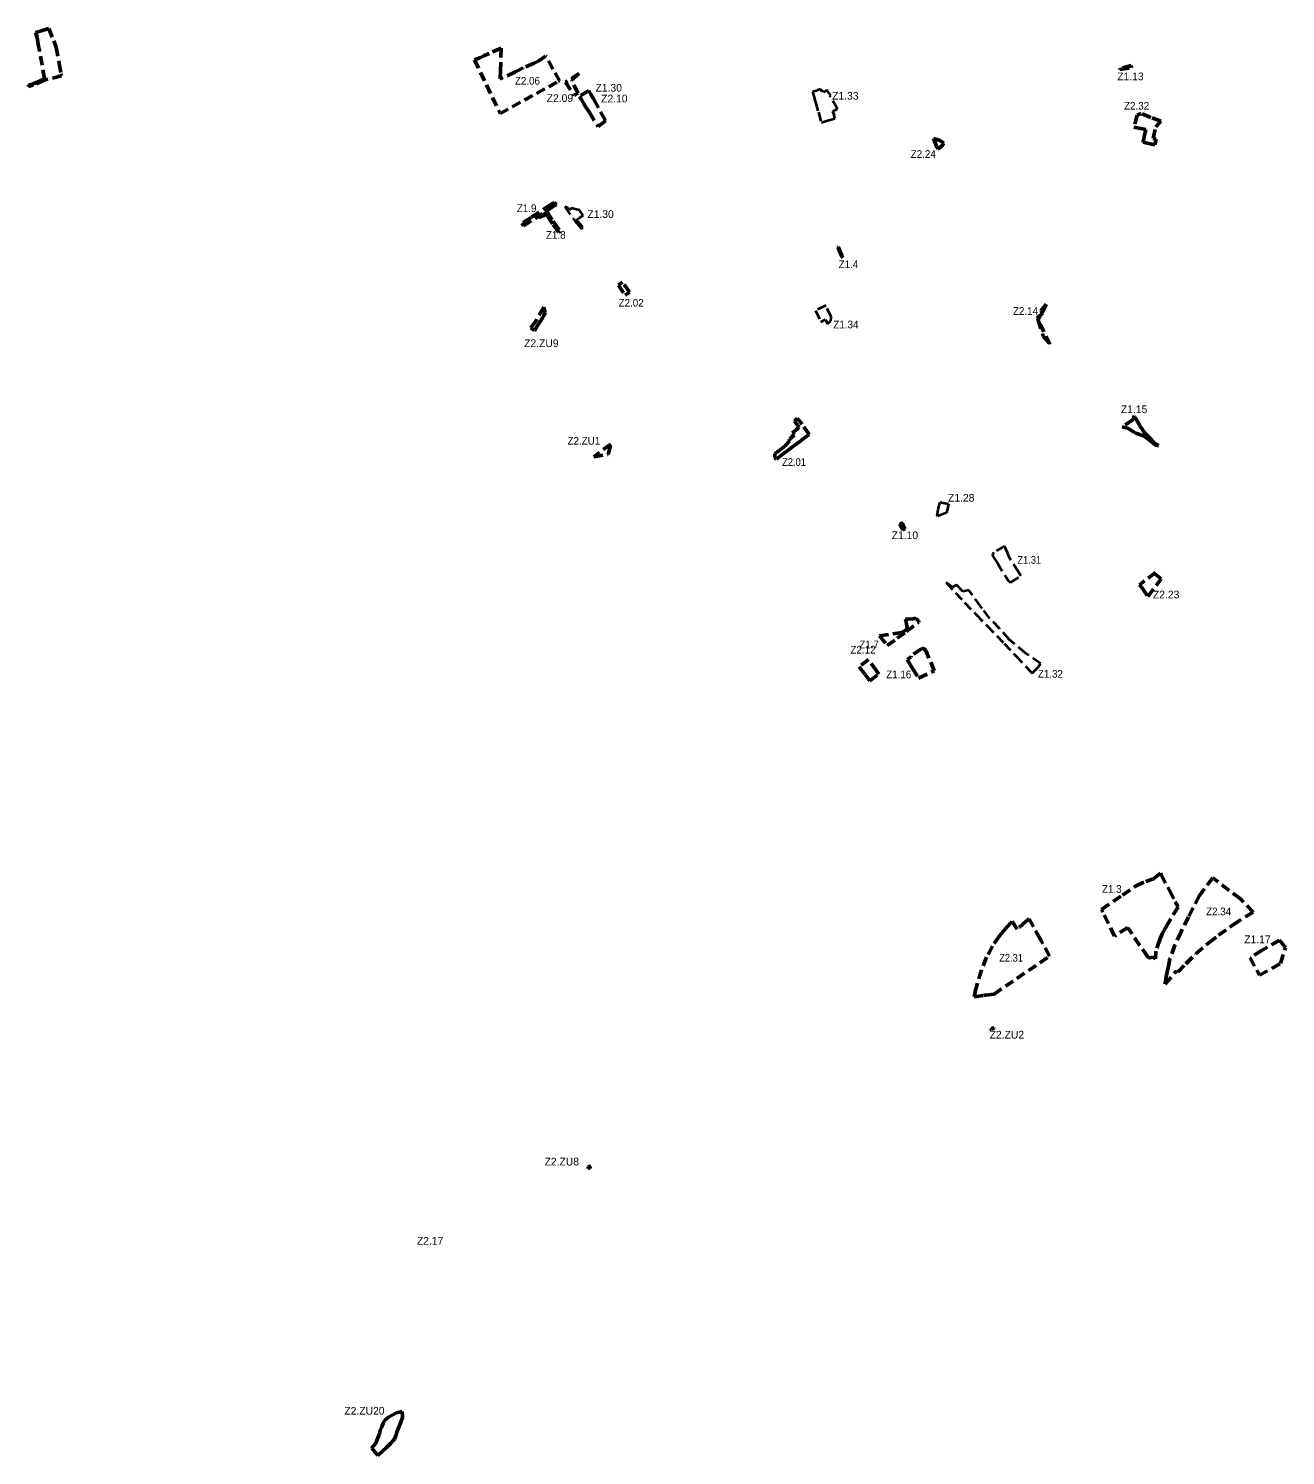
# Model space of a CAD drawing. Extents: x -650368 to -643203, y -1074215 to -1066658.
# Drawn here: x -649708 to -646290, y -1074215 to -1070336 of the extents above; entities that cross this region are included whole.
import ezdxf
from ezdxf.enums import TextEntityAlignment as Align

# ---------------------------------------------------------------- set-up
doc = ezdxf.new("R2010")
doc.units = 0
doc.header["$LTSCALE"] = 8.4
doc.linetypes.add('MEDIUM_DASHED', pattern=[4.5, 3, -1.5])
for name, color, linetype, lineweight in [('57', 7, 'MEDIUM_DASHED', 40), ('58', 7, 'MEDIUM_DASHED', 53), ('59', 7, 'MEDIUM_DASHED', 53)]:
    doc.layers.add(name, color=color, linetype=linetype, lineweight=lineweight)
for name, color, linetype in [('60', 7, 'Continuous'), ('61', 7, 'Continuous'), ('62', 7, 'Continuous')]:
    doc.layers.add(name, color=color, linetype=linetype)

msp = doc.modelspace()

# ---------------------------------------------------------------- linework, layer by layer
at = {"layer": '57', "lineweight": 53}
for points in [[(-649689.02, -1070346.94), (-649670.28, -1070341.35), (-649653.03, -1070336.2), (-649639.561, -1070370), (-649633, -1070386.46), (-649624.97, -1070431.24), (-649620.17, -1070459.09), (-649619.72, -1070461.73), (-649618.85, -1070465.12), (-649663.84, -1070475.94), (-649695.44, -1070490.03), (-649708.08, -1070493.61), (-649708.37, -1070489.38), (-649702.69, -1070488.94), (-649686.94, -1070482.59), (-649664.82, -1070473.32), (-649678.92, -1070395.81), (-649680.99, -1070384.52), (-649683.08, -1070373.11), (-649685.31, -1070360.88)], [(-646739.83, -1070444.94), (-646739.74, -1070447.98), (-646708.18, -1070442.69), (-646708.99, -1070436.76)], [(-648366.98, -1070865.44), (-648362.519, -1070872.788), (-648303.624, -1070834.844), (-648283.19, -1070821.23), (-648272.45, -1070814.075), (-648278.832, -1070808.761), (-648282.44, -1070810.84), (-648287.74, -1070814.32), (-648341.58, -1070849.98)], [(-648320.02, -1070850.16), (-648297.39, -1070835.36), (-648281.37, -1070860.23), (-648279.39, -1070862.98), (-648262.4, -1070886.58), (-648267.24, -1070889.9), (-648283.46, -1070865.74), (-648284.02, -1070864.91), (-648298.78, -1070842.92), (-648305.33, -1070843.62)], [(-647507.79, -1070930.48), (-647506.58, -1070929.86), (-647493.71, -1070959.89), (-647495.91, -1070955.93), (-647496.37, -1070956.17)], [(-647330.34, -1071678.82), (-647339.211, -1071683.431), (-647330.73, -1071700.09), (-647324.21, -1071696.2), (-647331.65, -1071681.7)], [(-647393.87, -1071987.45), (-647372.56, -1072013.58), (-647345.75, -1071993.72), (-647320.41, -1071975.27), (-647287.04, -1071950.34), (-647287.83, -1071945.52), (-647294.62, -1071939.95), (-647299.8, -1071940.18), (-647303.12, -1071940.66), (-647311.9, -1071942.01), (-647322.73, -1071940.89), (-647322.26, -1071943.87), (-647321.38, -1071949.5), (-647320.37, -1071955.14), (-647319.44, -1071960.39), (-647318.12, -1071967.77), (-647332.2, -1071978.11)], [(-646789.83, -1072730.68), (-646732.95, -1072691.68), (-646697.89, -1072667.65), (-646669.6, -1072654.53), (-646648.27, -1072647.48), (-646629.86, -1072632.07), (-646627.32, -1072636.95), (-646605.23, -1072679.37), (-646589.37, -1072709.83), (-646581.92, -1072723.91), (-646612.11, -1072774.56), (-646612.76, -1072775.67), (-646612.4, -1072775.05), (-646616.6, -1072782.31), (-646616.97, -1072782.9), (-646624.81, -1072797.42), (-646631.08, -1072812.68), (-646642.404, -1072844.195), (-646643.445, -1072864.732), (-646651.14, -1072860.57), (-646662.12, -1072863.28), (-646664.42, -1072859.9), (-646716.21, -1072783.78), (-646718.72, -1072780.09), (-646754.96, -1072803.29), (-646786.56, -1072737.88)], [(-646360.22, -1072909.57), (-646303.02, -1072877.74), (-646289.63, -1072834.04), (-646305.56, -1072814.43), (-646353.25, -1072841.63), (-646385.86, -1072862.59)]]:
    msp.add_lwpolyline(points, close=True, dxfattribs=at)
at = {"layer": '57'}
for points in [[(-647537.02, -1070503.71), (-647546, -1070508.8), (-647547.21, -1070505.8), (-647551.72, -1070507.63), (-647554.53, -1070500.69), (-647562.6, -1070503.96), (-647562.41, -1070504.46), (-647575.92, -1070508.61), (-647572.58, -1070520.08), (-647569.96, -1070529.21), (-647570.25, -1070529.29), (-647569.06, -1070533.49), (-647568.31, -1070536.13), (-647560.15, -1070563.59), (-647551.93, -1070591.24), (-647538.02, -1070587.26), (-647515.53, -1070580.81), (-647517.04, -1070572.92), (-647515.92, -1070572.48), (-647521.04, -1070561.51), (-647511.26, -1070556.25), (-647507.74, -1070554.36), (-647527.28, -1070521.45), (-647528.84, -1070518.82), (-647526.64, -1070517.92), (-647535.34, -1070505.95)], [(-648207.151, -1070878.029), (-648205.18, -1070880.5), (-648200.86, -1070877.05), (-648202.798, -1070874.754), (-648212.94, -1070862.74), (-648217.85, -1070856.93), (-648218.11, -1070856.44), (-648209.37, -1070850.44), (-648200.17, -1070844.094), (-648209.66, -1070829.88), (-648221.58, -1070827.03), (-648231.22, -1070824.92), (-648237.46, -1070829.68), (-648241.96, -1070823.46), (-648249.5, -1070821.08), (-648222.158, -1070859.221), (-648217.1, -1070865.56)], [(-647229.63, -1071623.27), (-647206.3, -1071628.17), (-647209.092, -1071641.463), (-647211.91, -1071652.25), (-647217.42, -1071654.54), (-647234.94, -1071661.83), (-647237.25, -1071659.7), (-647233.89, -1071643.39), (-647230.86, -1071629.13)], [(-647184.81, -1071848.61), (-647185.62, -1071849.12), (-647194.96, -1071854.93), (-647205.62, -1071847.24), (-647212.66, -1071842.15), (-647163.08, -1071896.13), (-647131.146, -1071929.146), (-647101.07, -1071960.24), (-647055.16, -1072007.74), (-647023.04, -1072041.63), (-646981.35, -1072085.77), (-646978.602, -1072088.66), (-646962.041, -1072072.379), (-646956.04, -1072061.95), (-646996.8, -1072034.35), (-647040.89, -1071996.58), (-647067.53, -1071967.54), (-647095.51, -1071938.39), (-647114.479, -1071912.479), (-647118.79, -1071906.59), (-647151.07, -1071863.08), (-647167.15, -1071866.22)]]:
    msp.add_lwpolyline(points, close=True, dxfattribs=at)
for points in [[(-647539.818, -1071089.2), (-647568.01, -1071102.98), (-647553.01, -1071133.68)], [(-647525.1, -1071121.25), (-647524.95, -1071119.68), (-647539.817, -1071089.199)], [(-647553.01, -1071133.68), (-647540.48, -1071127.55), (-647534.851, -1071139.015), (-647526.04, -1071130.94), (-647525.1, -1071121.25)], [(-647053.43, -1071743.63), (-647083.97, -1071760.74), (-647084.95, -1071761.98), (-647085.71, -1071763.75), (-647086.19, -1071766.95), (-647085.25, -1071770.69), (-647074.99, -1071786.99)], [(-647009.514, -1071823.81), (-647016.12, -1071813.35), (-647039.14, -1071776.9), (-647044.83, -1071763.37), (-647053.43, -1071743.63)], [(-647074.99, -1071786.99), (-647073.19, -1071789.9), (-647044.12, -1071836.68)], [(-647044.12, -1071836.68), (-647040.2, -1071839.6), (-647037.23, -1071841.82), (-647009.514, -1071823.81)]]:
    msp.add_lwpolyline(points, dxfattribs=at)
at = {"layer": '57', "lineweight": 53}
for points in [[(-646669.77, -1071438.64), (-646671.02, -1071436.82), (-646686.04, -1071415.05), (-646701.52, -1071388.41), (-646703.84, -1071399.38), (-646704.58, -1071400.2), (-646734, -1071419.27), (-646719.23, -1071422.46), (-646715.7, -1071424.14), (-646703.15, -1071432.76), (-646696.59, -1071435.91), (-646678.5, -1071442.87)], [(-646678.5, -1071442.87), (-646673.89, -1071444.28), (-646670.05, -1071447.06), (-646662.55, -1071453.44), (-646655.29, -1071458.37), (-646643.4, -1071468.99), (-646638.52, -1071470.05), (-646634.56, -1071469.49), (-646645.57, -1071462.96), (-646654.25, -1071454.23), (-646669.77, -1071438.64)], [(-647271.92, -1072022.5), (-647274.99, -1072021.69), (-647277.91, -1072021.81), (-647280.99, -1072022.86), (-647308.09, -1072041.53), (-647308.4, -1072044.8), (-647318.52, -1072051.32)], [(-647287.34, -1072101.88), (-647244.88, -1072082.33), (-647267.71, -1072027.09)], [(-647267.71, -1072027.09), (-647269.43, -1072024.67), (-647271.92, -1072022.5)], [(-647318.52, -1072051.32), (-647315.92, -1072055.47), (-647303.63, -1072075.43), (-647287.34, -1072101.88)]]:
    msp.add_lwpolyline(points, dxfattribs=at)
at = {"layer": '58'}
for points in [[(-648495.666, -1070421.476), (-648425.835, -1070567.021), (-648267.801, -1070480.55), (-648263.859, -1070478.393), (-648282.01, -1070446.35), (-648302.01, -1070411.05), (-648320.24, -1070423.64), (-648332.97, -1070430.18), (-648362.79, -1070443.63), (-648363.1, -1070443.1), (-648383.61, -1070453.86), (-648426.05, -1070473.34), (-648425.71, -1070468.87), (-648424.47, -1070452.7), (-648423.56, -1070413.35), (-648423.005, -1070389.357), (-648455.85, -1070404.19), (-648457.94, -1070405.13), (-648469.77, -1070410.47), (-648481.18, -1070415.62)], [(-648184.54, -1070505.07), (-648210.19, -1070521.07), (-648203.83, -1070531.25), (-648197.59, -1070541.27), (-648190.71, -1070552.3), (-648182.98, -1070564.68), (-648159.23, -1070602.75), (-648138.93, -1070587.1), (-648140.05, -1070585.09), (-648166.63, -1070537.28), (-648172.96, -1070525.9), (-648178.7, -1070515.58), (-648184.54, -1070505.07)], [(-646701.87, -1070603.92), (-646693.18, -1070605.83), (-646669.59, -1070611.01), (-646672.13, -1070622.41), (-646672.99, -1070626.23), (-646673.91, -1070630.38), (-646675.27, -1070636.43), (-646676.81, -1070643.36), (-646677.13, -1070644.78), (-646665.42, -1070647.54), (-646645.03, -1070652.34), (-646641.09, -1070636.89), (-646649.71, -1070634.85), (-646642.32, -1070603.3), (-646628.69, -1070588.27), (-646655.95, -1070577.64), (-646682.29, -1070567.36), (-646692.98, -1070571.45)], [(-647245.6, -1070636.4), (-647246.49, -1070638.53), (-647241.89, -1070648.94), (-647237.61, -1070658.33), (-647235.02, -1070664.1), (-647227.76, -1070658.33), (-647224.57, -1070655.48), (-647224.37, -1070655.59), (-647218.44, -1070647.43), (-647229.34, -1070640.91), (-647243.28, -1070636.43)], [(-648341.943, -1071150.071), (-648333.002, -1071157.07), (-648330.78, -1071154.36), (-648324.82, -1071145.25), (-648319.77, -1071137.52), (-648309.41, -1071121.655), (-648307.33, -1071118.47), (-648303.08, -1071108.16), (-648306.31, -1071097.36), (-648305.83, -1071096.48), (-648306.39, -1071093.99), (-648326.92, -1071128.68), (-648328.9, -1071132.02), (-648332.09, -1071136.43)], [(-646940.67, -1071085.15), (-646955.39, -1071103.23), (-646951.831, -1071107.765), (-646955.138, -1071114.466), (-646960.72, -1071117.25), (-646964.973, -1071123.095), (-646964.291, -1071125.474), (-646962.591, -1071128.96), (-646948.286, -1071172.534), (-646929.64, -1071194.58), (-646955.2, -1071143.67), (-646962.471, -1071129.325), (-646955.138, -1071114.466), (-646949.12, -1071111.22), (-646951.831, -1071107.765)], [(-647597.54, -1071448.75), (-647585.273, -1071440.044), (-647603.9, -1071412.1), (-647617.49, -1071394.901), (-647625.428, -1071403.267), (-647612.269, -1071419.742), (-647616.75, -1071423.83), (-647619.75, -1071426.57), (-647626.65, -1071432.87), (-647630.04, -1071435.97), (-647626.34, -1071440.73), (-647628.21, -1071443.09), (-647631.16, -1071445.79), (-647634.12, -1071448.49), (-647638.4, -1071452.55), (-647639.11, -1071452.78), (-647639.64, -1071453.33), (-647636.48, -1071457.52), (-647640.04, -1071458.97), (-647651.2, -1071471.24), (-647664.16, -1071481.45), (-647678.56, -1071492.25), (-647678.3, -1071502.55), (-647676.51, -1071504.34), (-647674.28, -1071506.59), (-647655.59, -1071492.52), (-647642.45, -1071482.62), (-647626.7, -1071470.46), (-647611.82, -1071459.38)], [(-648170.93, -1071500), (-648132.14, -1071493.74), (-648125, -1071465.96)], [(-646664.304, -1071879.909), (-646627.89, -1071832.14), (-646645.26, -1071818.72), (-646643.11, -1071814.6), (-646686.45, -1071848.26), (-646680.17, -1071856.05)], [(-647449.29, -1072071.08), (-647433.06, -1072092.41), (-647419.85, -1072109.65), (-647395.88, -1072091.34), (-647401.58, -1072082.32), (-647423.49, -1072051.76)], [(-646987.154, -1072756.377), (-646995.02, -1072762.45), (-647019.06, -1072784.57), (-647032.7, -1072763.68), (-647050.51, -1072782.79), (-647063.04, -1072796.74), (-647067.22, -1072802.77), (-647086.65, -1072830.76), (-647102.38, -1072860.7), (-647116.33, -1072895.3), (-647132.47, -1072950.4), (-647136.39, -1072968.63), (-647110.32, -1072964.56), (-647107.01, -1072964.04), (-647105.4, -1072963.84), (-647082.36, -1072960.95), (-646931.1, -1072857.55), (-646954.51, -1072815.63), (-646956.845, -1072810.746)], [(-647092.58, -1073058.59), (-647092.67, -1073058), (-647090.83, -1073057.72)], [(-647087.96, -1073056.29), (-647088.34, -1073053.92), (-647081.66, -1073052.93), (-647081.63, -1073053.13)], [(-648179.07, -1073428.81), (-648183.46, -1073429.52), (-648186.46, -1073430.01), (-648185.82, -1073435.12), (-648182.81, -1073434.38)], [(-648695.83, -1074124.88), (-648700.77, -1074138.18), (-648705.61, -1074149.4), (-648709.34, -1074161.26), (-648712.77, -1074170.51), (-648715.37, -1074173.28), (-648723.64, -1074182.09), (-648730.34, -1074189.22), (-648733.69, -1074192.38), (-648745.22, -1074203.28), (-648758.41, -1074215.05), (-648775.1, -1074194.97), (-648763.85, -1074181.6), (-648758.05, -1074167.41), (-648753.74, -1074156.28), (-648751.97, -1074146.03), (-648747.25, -1074137.56), (-648743.55, -1074127.69), (-648739.31, -1074119.01), (-648729.24, -1074110.84), (-648707.44, -1074098.79), (-648691.9, -1074095.66), (-648690.92, -1074111.64)]]:
    msp.add_lwpolyline(points, close=True, dxfattribs=at)
at = {"layer": '59'}
for points in [[(-648247.67, -1070481.57), (-648223.98, -1070518.025), (-648221.359, -1070516.349), (-648215.48, -1070512.59), (-648214.34, -1070511.86), (-648231.53, -1070476.99), (-648210.48, -1070458.42)], [(-648104.12, -1071033.78), (-648085.73, -1071060.92), (-648074.121, -1071052.749), (-648092.72, -1071025.89)], [(-646486.95, -1072644.87), (-646523.5, -1072692.86), (-646553.12, -1072751.12), (-646573.72, -1072791.74), (-646590.21, -1072827.45), (-646603.99, -1072863.84), (-646607.94, -1072885.41), (-646611.51, -1072900.28), (-646614.73, -1072918.29), (-646616.49, -1072934), (-646586.22, -1072897.88), (-646582.8, -1072901.17), (-646560.75, -1072878.59), (-646533.57, -1072851.83), (-646498.43, -1072821.57), (-646471.68, -1072801.15), (-646431.37, -1072771.48), (-646395.56, -1072748.73), (-646377.69, -1072738.13), (-646412.35, -1072701.92)]]:
    msp.add_lwpolyline(points, close=True, dxfattribs=at)

# ---------------------------------------------------------------- texts
at = {"layer": '60'}
for s, p in [('Z1.13', (-646711.241, -1070476.795)), ('Z1.30', (-648130.25, -1070507.749)), ('Z1.33', (-647486.769, -1070529.43)), ('Z1.30', (-648152.527, -1070851.191)), ('Z1.15', (-646701.349, -1071381.596)), ('Z1.28', (-647171.469, -1071622.255)), ('Z1.10', (-647324.762, -1071724.226)), ('Z1.17', (-646365.85, -1072822.584))]:
    msp.add_text(s, height=21, dxfattribs=at).set_placement(p, align=Align.CENTER)
for s, width, p in [('Z1.9', 0.95, (-648353.632, -1070835.005)), ('Z1.8', 0.95, (-648274.243, -1070907.64)), ('Z1.4', 0.95, (-647478.395, -1070987.579)), ('Z1.34', 0.95, (-647485.061, -1071151.263)), ('Z1.31', 0.9, (-646986.497, -1071791.238)), ('Z1.7', 0.95, (-647422.127, -1072021.075)), ('Z1.16', 0.95, (-647341.512, -1072102.293)), ('Z1.32', 0.95, (-646928.965, -1072100.798)), ('Z1.3', 0.95, (-646762.051, -1072685.488))]:
    msp.add_text(s, height=21, dxfattribs=dict(at, width=width)).set_placement(p, align=Align.CENTER)
at = {"layer": '61'}
for s, width, p in [('Z2.06', 0.95, (-648351.384, -1070488.722)), ('Z2.32', 0.95, (-646694.585, -1070556.682)), ('Z2.24', 0.95, (-647274.804, -1070687.883)), ('Z2.14', 0.95, (-646996.763, -1071114.597)), ('Z2.ZU1', 0.95, (-648197.892, -1071467.275)), ('Z2.01', 0.9, (-647626.341, -1071525.223)), ('Z2.12', 0.95, (-647438.697, -1072035.236)), ('Z2.31', 0.9, (-647035.914, -1072872.757))]:
    msp.add_text(s, height=21, dxfattribs=dict(at, width=width)).set_placement(p, align=Align.CENTER)
for s, p in [('Z2.10', (-648115.069, -1070536.986)), ('Z2.ZU9', (-648313.517, -1071202.172)), ('Z2.23', (-646614.24, -1071885.289)), ('Z2.ZU2', (-647047.431, -1073081.819)), ('Z2.ZU8', (-648257.993, -1073426.743)), ('Z2.ZU20', (-648794.75, -1074104.169))]:
    msp.add_text(s, height=21, dxfattribs=at).set_placement(p, align=Align.CENTER)
at = {"layer": '62'}
for s, p in [('Z2.09', (-648263.112, -1070535.96)), ('Z2.17', (-648616.086, -1073642.104))]:
    msp.add_text(s, height=21, dxfattribs=at).set_placement(p, align=Align.CENTER)
at = {"layer": '62', "width": 0.95}
for s, p in [('Z2.02', (-648069.383, -1071092.212)), ('Z2.34', (-646471.455, -1072746.692))]:
    msp.add_text(s, height=21, dxfattribs=at).set_placement(p, align=Align.CENTER)

doc.saveas('drawing.dxf')
